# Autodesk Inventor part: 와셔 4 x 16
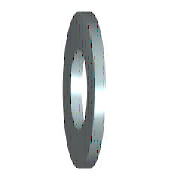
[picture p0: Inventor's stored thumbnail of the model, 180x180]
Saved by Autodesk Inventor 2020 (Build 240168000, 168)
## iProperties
IsCustomPart: 1
Created: 2012-02
Part Number: 와셔 4 x 16
Material: 강철, 연강
Description: 미터법 평면 와셔
Document SubType Name: Modeling
Standard: ANSI B18.22M
Designer: mduedu
Standard Revision: 1999
Standards Organization: ANSI
Language: ko-KR
Size Designation: 4 W
Categories: <MemberInstance><Categories><Category DisplayName="조임쇠" InternalName="e4da775c-781d-43d5-af7c-5136215cf5a6" Mnemonic="FSTN"><Category DisplayName="와셔" InternalN
Density: 1 g/cm^3
Appearance: 파란색 - 벽 페인트 - 광택
Author: mduedu
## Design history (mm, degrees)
sketch "스케치"
  geometry: C1 r 8 at (0, 0); C2 r 2.35 at (0, 0); 1 further point
  constraints: 2 centre point, 2 coincident
  dimensions: "d0" = 4.7 diameter of C2 (= SD1); "d1" = 16 diameter of C1 (= SD2)
extrude "본체" new body sketch "스케치" distance "d2" = 2.3 (= SD); taper "d3" = 0 deg
workaxis "Work Axis1"
workplane "Work Plane1"
body "Solid1"
other parameters: "SD1" = 4.7 [user parameter; used in 1 equation term], "SD2" = 16 [user parameter; used in 1 equation term], "SD" = 2.3 [user parameter; used in 1 equation term], "d4" = 0, "d5" = 0, "d6" = 0, "d7" = 0, "NND" = 4 [user parameter]
